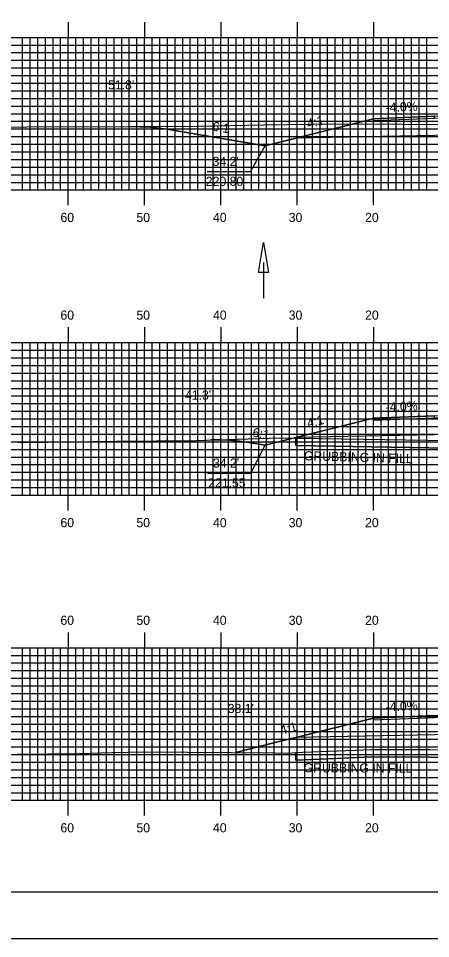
# Model space of a CAD drawing. Extents: x 1804684 to 1805027, y 442591 to 442811.
# Drawn here: x 1804783.1 to 1804837.2, y 442590.5 to 442711.2 of the extents above; entities that cross this region are included whole.
import ezdxf

# ---------------------------------------------------------------- set-up
doc = ezdxf.new("R2010")
doc.units = 0
for name, color, linetype in [('ANNOTATION', 7, 'Continuous'), ('BORDER', 7, 'Continuous'), ('D_Drainage_Ditch_Line', 7, 'Continuous'), ('D_Roadway_Centerline', 7, 'Continuous'), ('D_Roadway_Edge_Shoulder', 7, 'Continuous'), ('D_Roadway_SlopeLines', 7, 'Continuous'), ('D_Roadway_SubGrade', 7, 'Continuous'), ('D_Text_Standard', 7, 'Continuous'), ('GRUBBING IN FILL', 7, 'Continuous'), ('H_V ANNOTATION', 7, 'Continuous'), ('MAJOR', 7, 'Continuous'), ('MINOR', 7, 'Continuous'), ('PLOT BOUNDARY', 7, 'Continuous'), ('S_Roadway_Centerline', 7, 'Continuous')]:
    doc.layers.add(name, color=color, linetype=linetype)

msp = doc.modelspace()

# ---------------------------------------------------------------- linework, layer by layer
at = {"layer": 'ANNOTATION'}
for points in [[(1804807.87, 442691.09), (1804813.56, 442691.09), (1804815.51, 442694.47)], [(1804807.91, 442651.56), (1804813.61, 442651.56), (1804815.51, 442655.21)]]:
    msp.add_lwpolyline(points, dxfattribs=at)
at = {"layer": 'BORDER'}
msp.add_lwpolyline([(1804700.08, 442596.67), (1805020.08, 442596.67), (1805020.08, 442806.67), (1804700.08, 442806.67)], close=True, dxfattribs=at)
at = {"layer": 'D_Drainage_Ditch_Line'}
msp.add_line((1804815.28, 442679.18), (1804815.28, 442674.48), dxfattribs=at)
msp.add_lwpolyline([(1804815.94, 442677.86), (1804814.63, 442677.86), (1804815.28, 442681.8)], close=True, dxfattribs=at)
at = {"layer": 'D_Roadway_Centerline'}
for points in [[(1804797.85, 442696.98), (1804799.1, 442696.96), (1804800.35, 442696.89), (1804801.6, 442696.76), (1804802.85, 442696.58), (1804815.51, 442694.47), (1804819.51, 442695.47), (1804829.68, 442698.01), (1804837.68, 442698.33), (1804849.68, 442698.62), (1804861.68, 442698.91), (1804869.68, 442698.59), (1804879.85, 442696.04), (1804883.85, 442695.04), (1804901.29, 442697.95), (1804902.54, 442698.13), (1804903.79, 442698.25), (1804905.04, 442698.31), (1804906.29, 442698.31)], [(1804808.37, 442655.9), (1804809.62, 442655.91), (1804810.87, 442655.86), (1804812.12, 442655.74), (1804813.37, 442655.57), (1804815.51, 442655.21), (1804819.51, 442656.21), (1804829.68, 442658.75), (1804837.68, 442659.07), (1804849.68, 442659.36), (1804861.68, 442659.65), (1804869.68, 442659.33), (1804879.85, 442656.79), (1804883.85, 442655.79), (1804888.24, 442656.52), (1804889.49, 442656.7), (1804890.74, 442656.83), (1804891.99, 442656.91), (1804893.24, 442656.94)], [(1804811.62, 442614.93), (1804817.68, 442616.45), (1804819.51, 442616.91), (1804829.68, 442619.45), (1804837.68, 442619.77), (1804849.68, 442620.06), (1804861.68, 442620.35), (1804869.68, 442620.03), (1804879.85, 442617.48), (1804887.96, 442615.46)]]:
    msp.add_lwpolyline(points, dxfattribs=at)
at = {"layer": 'D_Roadway_Edge_Shoulder'}
for points in [[(1804837.68, 442698.33), (1804829.68, 442698.01), (1804829.68, 442697.76), (1804837.68, 442698.08)], [(1804837.68, 442659.07), (1804829.68, 442658.75), (1804829.68, 442658.5), (1804837.68, 442658.82)], [(1804837.68, 442619.77), (1804829.68, 442619.45), (1804829.68, 442619.2), (1804837.68, 442619.52)]]:
    msp.add_lwpolyline(points, close=True, dxfattribs=at)
at = {"layer": 'D_Roadway_SlopeLines'}
for points in [[(1804829.68, 442698.01), (1804815.51, 442694.47)], [(1804815.51, 442694.47), (1804802.85, 442696.58), (1804801.6, 442696.76), (1804800.35, 442696.89), (1804799.1, 442696.96), (1804797.85, 442696.98)], [(1804829.68, 442658.75), (1804815.51, 442655.21)], [(1804815.51, 442655.21), (1804813.37, 442655.57), (1804812.12, 442655.74), (1804810.87, 442655.86), (1804809.62, 442655.91), (1804808.37, 442655.9)], [(1804815.51, 442655.21), (1804812.12, 442655.74), (1804810.87, 442655.86), (1804809.62, 442655.91), (1804808.37, 442655.9)], [(1804829.68, 442619.45), (1804819.51, 442616.91), (1804817.68, 442616.45), (1804811.62, 442614.93)]]:
    msp.add_lwpolyline(points, dxfattribs=at)
at = {"layer": 'D_Roadway_SubGrade'}
for points in [[(1804837.68, 442695.83), (1804819.51, 442695.47), (1804829.68, 442698.01), (1804829.68, 442697.76), (1804837.68, 442698.08), (1804849.68, 442698.37), (1804861.68, 442698.66), (1804869.68, 442698.34), (1804869.68, 442698.59), (1804879.85, 442696.04), (1804861.68, 442696.41), (1804849.68, 442696.12)], [(1804837.68, 442656.57), (1804819.51, 442656.21), (1804829.68, 442658.75), (1804829.68, 442658.5), (1804837.68, 442658.82), (1804849.68, 442659.11), (1804861.68, 442659.4), (1804869.68, 442659.08), (1804869.68, 442659.33), (1804879.85, 442656.79), (1804861.68, 442657.15), (1804849.68, 442656.86)], [(1804837.68, 442617.27), (1804819.51, 442616.91), (1804829.68, 442619.45), (1804829.68, 442619.2), (1804837.68, 442619.52), (1804849.68, 442619.81), (1804861.68, 442620.1), (1804869.68, 442619.78), (1804869.68, 442620.03), (1804879.85, 442617.48), (1804861.68, 442617.85), (1804849.68, 442617.56)]]:
    msp.add_lwpolyline(points, close=True, dxfattribs=at)
at = {"layer": 'GRUBBING IN FILL'}
for p, q in [((1804819.51, 442656.16), (1804819.51, 442655.16)), ((1804819.51, 442656.16), (1804819.51, 442655.16)), ((1804819.51, 442614.93), (1804819.51, 442613.93)), ((1804819.51, 442614.93), (1804819.51, 442613.93))]:
    msp.add_line(p, q, dxfattribs=at)
for points in [[(1804819.51, 442656.16), (1804828.42, 442656.02), (1804839.46, 442655.84), (1804841.42, 442655.85), (1804849.68, 442656), (1804849.68, 442654.99), (1804841.43, 442654.85), (1804839.45, 442654.84), (1804829.48, 442655), (1804819.51, 442655.16)], [(1804819.51, 442656.16), (1804828.42, 442656.02), (1804839.46, 442655.84), (1804841.42, 442655.85), (1804849.68, 442656), (1804849.68, 442654.99), (1804841.43, 442654.85), (1804839.45, 442654.84), (1804829.48, 442655), (1804819.51, 442655.16)], [(1804819.51, 442614.93), (1804820.41, 442614.99), (1804824.93, 442615.17), (1804829.44, 442615.35), (1804833.26, 442615.34), (1804837.08, 442615.32), (1804840.97, 442615.2), (1804844.86, 442615.08), (1804849.68, 442615.12), (1804849.68, 442614.12), (1804844.85, 442614.08), (1804840.96, 442614.2), (1804837.06, 442614.32), (1804833.26, 442614.34), (1804829.46, 442614.35), (1804824.96, 442614.17), (1804819.51, 442613.93)], [(1804819.51, 442614.93), (1804820.41, 442614.99), (1804824.93, 442615.17), (1804829.44, 442615.35), (1804833.26, 442615.34), (1804837.08, 442615.32), (1804840.97, 442615.2), (1804844.86, 442615.08), (1804849.68, 442615.12), (1804849.68, 442614.12), (1804844.85, 442614.08), (1804840.96, 442614.2), (1804837.06, 442614.32), (1804833.26, 442614.34), (1804829.46, 442614.35), (1804824.96, 442614.17), (1804819.51, 442613.93)]]:
    msp.add_lwpolyline(points, close=True, dxfattribs=at)
for points in [[(1804819.51, 442655.16), (1804839.45, 442654.84), (1804840.48, 442654.85), (1804841.43, 442654.85), (1804858.38, 442655.14), (1804864.95, 442655.26), (1804865.14, 442655.25), (1804879.85, 442655.7)], [(1804819.51, 442655.16), (1804839.45, 442654.84), (1804840.48, 442654.85), (1804841.43, 442654.85), (1804858.38, 442655.14), (1804864.95, 442655.26), (1804865.14, 442655.25), (1804879.85, 442655.7)], [(1804819.51, 442613.93), (1804820.46, 442613.99), (1804829.46, 442614.35), (1804837.06, 442614.32), (1804844.85, 442614.08), (1804861.41, 442614.21), (1804867.45, 442614.4), (1804876.43, 442614.59), (1804879.85, 442614.57)], [(1804819.51, 442613.93), (1804820.46, 442613.99), (1804829.46, 442614.35), (1804837.06, 442614.32), (1804844.85, 442614.08), (1804861.41, 442614.21), (1804867.45, 442614.4), (1804876.43, 442614.59), (1804879.85, 442614.57)]]:
    msp.add_lwpolyline(points, dxfattribs=at)
at = {"layer": 'MAJOR'}
for p, q in [((1804789.68, 442710.67), (1804789.68, 442708.67)), ((1804799.68, 442710.67), (1804799.68, 442708.67)), ((1804809.68, 442710.67), (1804809.68, 442708.67)), ((1804819.68, 442710.67), (1804819.68, 442708.67)), ((1804829.68, 442710.67), (1804829.68, 442708.67)), ((1804709.68, 442708.67), (1804989.68, 442708.67)), ((1804709.68, 442708.67), (1804989.68, 442708.67)), ((1804789.68, 442688.67), (1804789.68, 442708.67)), ((1804799.68, 442688.67), (1804799.68, 442708.67)), ((1804809.68, 442688.67), (1804809.68, 442708.67)), ((1804819.68, 442688.67), (1804819.68, 442708.67)), ((1804829.68, 442688.67), (1804829.68, 442708.67)), ((1804709.68, 442703.67), (1804989.68, 442703.67)), ((1804709.68, 442698.67), (1804989.68, 442698.67)), ((1804709.68, 442693.67), (1804989.68, 442693.67)), ((1804709.68, 442688.67), (1804989.68, 442688.67)), ((1804709.68, 442688.67), (1804989.68, 442688.67)), ((1804789.68, 442686.66), (1804789.68, 442688.67)), ((1804799.68, 442686.66), (1804799.68, 442688.67)), ((1804809.68, 442686.66), (1804809.68, 442688.67)), ((1804819.68, 442686.66), (1804819.68, 442688.67)), ((1804829.68, 442686.66), (1804829.68, 442688.67)), ((1804789.68, 442670.67), (1804789.68, 442668.67)), ((1804799.68, 442670.67), (1804799.68, 442668.67)), ((1804809.68, 442670.67), (1804809.68, 442668.67)), ((1804819.68, 442670.67), (1804819.68, 442668.67)), ((1804829.68, 442670.67), (1804829.68, 442668.67)), ((1804709.68, 442668.67), (1804989.68, 442668.67)), ((1804709.68, 442668.67), (1804989.68, 442668.67)), ((1804789.68, 442648.67), (1804789.68, 442668.67)), ((1804799.68, 442648.67), (1804799.68, 442668.67)), ((1804809.68, 442648.67), (1804809.68, 442668.67)), ((1804819.68, 442648.67), (1804819.68, 442668.67)), ((1804829.68, 442648.67), (1804829.68, 442668.67)), ((1804709.68, 442663.67), (1804989.68, 442663.67)), ((1804709.68, 442658.67), (1804989.68, 442658.67)), ((1804709.68, 442653.67), (1804989.68, 442653.67)), ((1804709.68, 442648.67), (1804989.68, 442648.67)), ((1804709.68, 442648.67), (1804989.68, 442648.67)), ((1804789.68, 442646.66), (1804789.68, 442648.67)), ((1804799.68, 442646.66), (1804799.68, 442648.67)), ((1804809.68, 442646.66), (1804809.68, 442648.67)), ((1804819.68, 442646.66), (1804819.68, 442648.67)), ((1804829.68, 442646.66), (1804829.68, 442648.67)), ((1804789.68, 442630.67), (1804789.68, 442628.67)), ((1804799.68, 442630.67), (1804799.68, 442628.67)), ((1804809.68, 442630.67), (1804809.68, 442628.67)), ((1804819.68, 442630.67), (1804819.68, 442628.67)), ((1804829.68, 442630.67), (1804829.68, 442628.67)), ((1804709.68, 442628.67), (1804989.68, 442628.67)), ((1804709.68, 442628.67), (1804989.68, 442628.67)), ((1804789.68, 442608.67), (1804789.68, 442628.67)), ((1804799.68, 442608.67), (1804799.68, 442628.67)), ((1804809.68, 442608.67), (1804809.68, 442628.67)), ((1804819.68, 442608.67), (1804819.68, 442628.67)), ((1804829.68, 442608.67), (1804829.68, 442628.67)), ((1804709.68, 442623.67), (1804989.68, 442623.67)), ((1804709.68, 442618.67), (1804989.68, 442618.67)), ((1804709.68, 442613.67), (1804989.68, 442613.67)), ((1804709.68, 442608.67), (1804989.68, 442608.67)), ((1804709.68, 442608.67), (1804989.68, 442608.67)), ((1804789.68, 442606.66), (1804789.68, 442608.67)), ((1804799.68, 442606.66), (1804799.68, 442608.67)), ((1804809.68, 442606.66), (1804809.68, 442608.67)), ((1804819.68, 442606.66), (1804819.68, 442608.67)), ((1804829.68, 442606.66), (1804829.68, 442608.67))]:
    msp.add_line(p, q, dxfattribs=at)
at = {"layer": 'MINOR'}
for p, q in [((1804783.68, 442688.67), (1804783.68, 442708.67)), ((1804784.68, 442688.67), (1804784.68, 442708.67)), ((1804785.68, 442688.67), (1804785.68, 442708.67)), ((1804786.68, 442688.67), (1804786.68, 442708.67)), ((1804787.68, 442688.67), (1804787.68, 442708.67)), ((1804788.68, 442688.67), (1804788.68, 442708.67)), ((1804790.68, 442688.67), (1804790.68, 442708.67)), ((1804791.68, 442688.67), (1804791.68, 442708.67)), ((1804792.68, 442688.67), (1804792.68, 442708.67)), ((1804793.68, 442688.67), (1804793.68, 442708.67)), ((1804794.68, 442688.67), (1804794.68, 442708.67)), ((1804795.68, 442688.67), (1804795.68, 442708.67)), ((1804796.68, 442688.67), (1804796.68, 442708.67)), ((1804797.68, 442688.67), (1804797.68, 442708.67)), ((1804798.68, 442688.67), (1804798.68, 442708.67)), ((1804800.68, 442688.67), (1804800.68, 442708.67)), ((1804801.68, 442688.67), (1804801.68, 442708.67)), ((1804802.68, 442688.67), (1804802.68, 442708.67)), ((1804803.68, 442688.67), (1804803.68, 442708.67)), ((1804804.68, 442688.67), (1804804.68, 442708.67)), ((1804805.68, 442688.67), (1804805.68, 442708.67)), ((1804806.68, 442688.67), (1804806.68, 442708.67)), ((1804807.68, 442688.67), (1804807.68, 442708.67)), ((1804808.68, 442688.67), (1804808.68, 442708.67)), ((1804810.68, 442688.67), (1804810.68, 442708.67)), ((1804811.68, 442688.67), (1804811.68, 442708.67)), ((1804812.68, 442688.67), (1804812.68, 442708.67)), ((1804813.68, 442688.67), (1804813.68, 442708.67)), ((1804814.68, 442688.67), (1804814.68, 442708.67)), ((1804815.68, 442688.67), (1804815.68, 442708.67)), ((1804816.68, 442688.67), (1804816.68, 442708.67)), ((1804817.68, 442688.67), (1804817.68, 442708.67)), ((1804818.68, 442688.67), (1804818.68, 442708.67)), ((1804820.68, 442688.67), (1804820.68, 442708.67)), ((1804821.68, 442688.67), (1804821.68, 442708.67)), ((1804822.68, 442688.67), (1804822.68, 442708.67)), ((1804823.68, 442688.67), (1804823.68, 442708.67)), ((1804824.68, 442688.67), (1804824.68, 442708.67)), ((1804825.68, 442688.67), (1804825.68, 442708.67)), ((1804826.68, 442688.67), (1804826.68, 442708.67)), ((1804827.68, 442688.67), (1804827.68, 442708.67)), ((1804828.68, 442688.67), (1804828.68, 442708.67)), ((1804830.68, 442688.67), (1804830.68, 442708.67)), ((1804831.68, 442688.67), (1804831.68, 442708.67)), ((1804832.68, 442688.67), (1804832.68, 442708.67)), ((1804833.68, 442688.67), (1804833.68, 442708.67)), ((1804834.68, 442688.67), (1804834.68, 442708.67)), ((1804835.68, 442688.67), (1804835.68, 442708.67)), ((1804836.68, 442688.67), (1804836.68, 442708.67)), ((1804709.68, 442707.67), (1804989.68, 442707.67)), ((1804709.68, 442706.67), (1804989.68, 442706.67)), ((1804709.68, 442705.67), (1804989.68, 442705.67)), ((1804709.68, 442704.67), (1804989.68, 442704.67)), ((1804709.68, 442702.67), (1804989.68, 442702.67)), ((1804709.68, 442701.67), (1804989.68, 442701.67)), ((1804709.68, 442700.67), (1804989.68, 442700.67)), ((1804709.68, 442699.67), (1804989.68, 442699.67)), ((1804709.68, 442697.67), (1804989.68, 442697.67)), ((1804709.68, 442696.67), (1804989.68, 442696.67)), ((1804709.68, 442695.67), (1804989.68, 442695.67)), ((1804709.68, 442694.67), (1804989.68, 442694.67)), ((1804709.68, 442692.67), (1804989.68, 442692.67)), ((1804709.68, 442691.67), (1804989.68, 442691.67)), ((1804709.68, 442690.67), (1804989.68, 442690.67)), ((1804709.68, 442689.67), (1804989.68, 442689.67)), ((1804783.68, 442648.67), (1804783.68, 442668.67)), ((1804784.68, 442648.67), (1804784.68, 442668.67)), ((1804785.68, 442648.67), (1804785.68, 442668.67)), ((1804786.68, 442648.67), (1804786.68, 442668.67)), ((1804787.68, 442648.67), (1804787.68, 442668.67)), ((1804788.68, 442648.67), (1804788.68, 442668.67)), ((1804790.68, 442648.67), (1804790.68, 442668.67)), ((1804791.68, 442648.67), (1804791.68, 442668.67)), ((1804792.68, 442648.67), (1804792.68, 442668.67)), ((1804793.68, 442648.67), (1804793.68, 442668.67)), ((1804794.68, 442648.67), (1804794.68, 442668.67)), ((1804795.68, 442648.67), (1804795.68, 442668.67)), ((1804796.68, 442648.67), (1804796.68, 442668.67)), ((1804797.68, 442648.67), (1804797.68, 442668.67)), ((1804798.68, 442648.67), (1804798.68, 442668.67)), ((1804800.68, 442648.67), (1804800.68, 442668.67)), ((1804801.68, 442648.67), (1804801.68, 442668.67)), ((1804802.68, 442648.67), (1804802.68, 442668.67)), ((1804803.68, 442648.67), (1804803.68, 442668.67)), ((1804804.68, 442648.67), (1804804.68, 442668.67)), ((1804805.68, 442648.67), (1804805.68, 442668.67)), ((1804806.68, 442648.67), (1804806.68, 442668.67)), ((1804807.68, 442648.67), (1804807.68, 442668.67)), ((1804808.68, 442648.67), (1804808.68, 442668.67)), ((1804810.68, 442648.67), (1804810.68, 442668.67)), ((1804811.68, 442648.67), (1804811.68, 442668.67)), ((1804812.68, 442648.67), (1804812.68, 442668.67)), ((1804813.68, 442648.67), (1804813.68, 442668.67)), ((1804814.68, 442648.67), (1804814.68, 442668.67)), ((1804815.68, 442648.67), (1804815.68, 442668.67)), ((1804816.68, 442648.67), (1804816.68, 442668.67)), ((1804817.68, 442648.67), (1804817.68, 442668.67)), ((1804818.68, 442648.67), (1804818.68, 442668.67)), ((1804820.68, 442648.67), (1804820.68, 442668.67)), ((1804821.68, 442648.67), (1804821.68, 442668.67)), ((1804822.68, 442648.67), (1804822.68, 442668.67)), ((1804823.68, 442648.67), (1804823.68, 442668.67)), ((1804824.68, 442648.67), (1804824.68, 442668.67)), ((1804825.68, 442648.67), (1804825.68, 442668.67)), ((1804826.68, 442648.67), (1804826.68, 442668.67)), ((1804827.68, 442648.67), (1804827.68, 442668.67)), ((1804828.68, 442648.67), (1804828.68, 442668.67)), ((1804830.68, 442648.67), (1804830.68, 442668.67)), ((1804831.68, 442648.67), (1804831.68, 442668.67)), ((1804832.68, 442648.67), (1804832.68, 442668.67)), ((1804833.68, 442648.67), (1804833.68, 442668.67)), ((1804834.68, 442648.67), (1804834.68, 442668.67)), ((1804835.68, 442648.67), (1804835.68, 442668.67)), ((1804836.68, 442648.67), (1804836.68, 442668.67)), ((1804709.68, 442667.67), (1804989.68, 442667.67)), ((1804709.68, 442666.67), (1804989.68, 442666.67)), ((1804709.68, 442665.67), (1804989.68, 442665.67)), ((1804709.68, 442664.67), (1804989.68, 442664.67)), ((1804709.68, 442662.67), (1804989.68, 442662.67)), ((1804709.68, 442661.67), (1804989.68, 442661.67)), ((1804709.68, 442660.67), (1804989.68, 442660.67)), ((1804709.68, 442659.67), (1804989.68, 442659.67)), ((1804709.68, 442657.67), (1804989.68, 442657.67)), ((1804709.68, 442656.67), (1804989.68, 442656.67)), ((1804709.68, 442655.67), (1804989.68, 442655.67)), ((1804709.68, 442654.67), (1804989.68, 442654.67)), ((1804709.68, 442652.67), (1804989.68, 442652.67)), ((1804709.68, 442651.67), (1804989.68, 442651.67)), ((1804709.68, 442650.67), (1804989.68, 442650.67)), ((1804709.68, 442649.67), (1804989.68, 442649.67)), ((1804783.68, 442608.67), (1804783.68, 442628.67)), ((1804784.68, 442608.67), (1804784.68, 442628.67)), ((1804785.68, 442608.67), (1804785.68, 442628.67)), ((1804786.68, 442608.67), (1804786.68, 442628.67)), ((1804787.68, 442608.67), (1804787.68, 442628.67)), ((1804788.68, 442608.67), (1804788.68, 442628.67)), ((1804790.68, 442608.67), (1804790.68, 442628.67)), ((1804791.68, 442608.67), (1804791.68, 442628.67)), ((1804792.68, 442608.67), (1804792.68, 442628.67)), ((1804793.68, 442608.67), (1804793.68, 442628.67)), ((1804794.68, 442608.67), (1804794.68, 442628.67)), ((1804795.68, 442608.67), (1804795.68, 442628.67)), ((1804796.68, 442608.67), (1804796.68, 442628.67)), ((1804797.68, 442608.67), (1804797.68, 442628.67)), ((1804798.68, 442608.67), (1804798.68, 442628.67)), ((1804800.68, 442608.67), (1804800.68, 442628.67)), ((1804801.68, 442608.67), (1804801.68, 442628.67)), ((1804802.68, 442608.67), (1804802.68, 442628.67)), ((1804803.68, 442608.67), (1804803.68, 442628.67)), ((1804804.68, 442608.67), (1804804.68, 442628.67)), ((1804805.68, 442608.67), (1804805.68, 442628.67)), ((1804806.68, 442608.67), (1804806.68, 442628.67)), ((1804807.68, 442608.67), (1804807.68, 442628.67)), ((1804808.68, 442608.67), (1804808.68, 442628.67)), ((1804810.68, 442608.67), (1804810.68, 442628.67)), ((1804811.68, 442608.67), (1804811.68, 442628.67)), ((1804812.68, 442608.67), (1804812.68, 442628.67)), ((1804813.68, 442608.67), (1804813.68, 442628.67)), ((1804814.68, 442608.67), (1804814.68, 442628.67)), ((1804815.68, 442608.67), (1804815.68, 442628.67)), ((1804816.68, 442608.67), (1804816.68, 442628.67)), ((1804817.68, 442608.67), (1804817.68, 442628.67)), ((1804818.68, 442608.67), (1804818.68, 442628.67)), ((1804820.68, 442608.67), (1804820.68, 442628.67)), ((1804821.68, 442608.67), (1804821.68, 442628.67)), ((1804822.68, 442608.67), (1804822.68, 442628.67)), ((1804823.68, 442608.67), (1804823.68, 442628.67)), ((1804824.68, 442608.67), (1804824.68, 442628.67)), ((1804825.68, 442608.67), (1804825.68, 442628.67)), ((1804826.68, 442608.67), (1804826.68, 442628.67)), ((1804827.68, 442608.67), (1804827.68, 442628.67)), ((1804828.68, 442608.67), (1804828.68, 442628.67)), ((1804830.68, 442608.67), (1804830.68, 442628.67)), ((1804831.68, 442608.67), (1804831.68, 442628.67)), ((1804832.68, 442608.67), (1804832.68, 442628.67)), ((1804833.68, 442608.67), (1804833.68, 442628.67)), ((1804834.68, 442608.67), (1804834.68, 442628.67)), ((1804835.68, 442608.67), (1804835.68, 442628.67)), ((1804836.68, 442608.67), (1804836.68, 442628.67)), ((1804709.68, 442627.67), (1804989.68, 442627.67)), ((1804709.68, 442626.67), (1804989.68, 442626.67)), ((1804709.68, 442625.67), (1804989.68, 442625.67)), ((1804709.68, 442624.67), (1804989.68, 442624.67)), ((1804709.68, 442622.67), (1804989.68, 442622.67)), ((1804709.68, 442621.67), (1804989.68, 442621.67)), ((1804709.68, 442620.67), (1804989.68, 442620.67)), ((1804709.68, 442619.67), (1804989.68, 442619.67)), ((1804709.68, 442617.67), (1804989.68, 442617.67)), ((1804709.68, 442616.67), (1804989.68, 442616.67)), ((1804709.68, 442615.67), (1804989.68, 442615.67)), ((1804709.68, 442614.67), (1804989.68, 442614.67)), ((1804709.68, 442612.67), (1804989.68, 442612.67)), ((1804709.68, 442611.67), (1804989.68, 442611.67)), ((1804709.68, 442610.67), (1804989.68, 442610.67)), ((1804709.68, 442609.67), (1804989.68, 442609.67))]:
    msp.add_line(p, q, dxfattribs=at)
at = {"layer": 'PLOT BOUNDARY'}
msp.add_lwpolyline([(1804683.89, 442590.55), (1805023.89, 442590.55), (1805023.89, 442810.55), (1804683.89, 442810.55)], close=True, dxfattribs=at)
at = {"layer": 'S_Roadway_Centerline'}
for points in [[(1804774.87, 442696.86), (1804784.25, 442696.94), (1804798.89, 442696.98), (1804806.64, 442697.05), (1804815.33, 442697.21), (1804821.41, 442697.28), (1804829.59, 442697.33), (1804837.34, 442697.27), (1804853.74, 442697.41), (1804861.11, 442698.35), (1804868.67, 442698.5), (1804876.82, 442697.88), (1804884.86, 442698.44), (1804889.08, 442698.45), (1804893.32, 442698.59), (1804906.83, 442698.3), (1804911.96, 442698.24)], [(1804772.62, 442656.11), (1804784.02, 442655.57), (1804795.94, 442655.76), (1804806.45, 442655.84), (1804817.38, 442656.2), (1804839.46, 442655.84), (1804840.47, 442655.85), (1804841.42, 442655.85), (1804858.36, 442656.14), (1804864.97, 442656.26), (1804865.15, 442656.25), (1804883.79, 442656.82), (1804887.57, 442656.93), (1804887.62, 442656.93), (1804887.64, 442656.93), (1804895.71, 442656.94), (1804911.53, 442656.95)], [(1804783.04, 442614.74), (1804791.17, 442614.81), (1804795.42, 442614.92), (1804799.52, 442615.02), (1804816.79, 442614.9), (1804818.39, 442614.86), (1804820.41, 442614.99), (1804829.44, 442615.35), (1804837.08, 442615.32), (1804844.86, 442615.08), (1804861.39, 442615.21), (1804867.42, 442615.4), (1804876.42, 442615.6), (1804884.65, 442615.53), (1804888.3, 442615.45), (1804892.04, 442615.5), (1804899.88, 442615.45), (1804908.7, 442615.36), (1804914.14, 442615.38)]]:
    msp.add_lwpolyline(points, dxfattribs=at)

# ---------------------------------------------------------------- texts
at = {"layer": 'ANNOTATION'}
for s, rotation, p in [('-4.0%', 2.2906, (1804831.31, 442698.88)), ('4:1', 14.0362, (1804821.13, 442696.74)), ('6:1', 350.5376, (1804808.51, 442696.46)), ('-4.0%', 2.2906, (1804831.31, 442659.62)), ('4:1', 14.0362, (1804821.13, 442657.48)), ('6:1', 350.5377, (1804813.77, 442656.33)), ('-4.0%', 2.2906, (1804831.31, 442620.32)), ('4:1', 14.0362, (1804817.6, 442617.26))]:
    msp.add_text(s, height=1.2, rotation=rotation, dxfattribs=at).set_placement(p)
for s, p in [("34.2'", (1804808.6, 442691.81)), ('220.80', (1804807.71, 442689.21)), ("34.2'", (1804808.65, 442652.28)), ('221.55', (1804808.02, 442649.68))]:
    msp.add_text(s, height=1.2, dxfattribs=at).set_placement(p)
at = {"layer": 'D_Text_Standard'}
for s, p in [("51.8'", (1804794.89, 442701.86)), ("41.3'", (1804804.98, 442661.19)), ("38.1'", (1804810.58, 442620.11))]:
    msp.add_text(s, height=1.2, dxfattribs=at).set_placement(p)
at = {"layer": 'GRUBBING IN FILL'}
for rotation, p in [(358.4339, (1804820.56, 442653.24)), (359.8053, (1804820.53, 442612.34))]:
    msp.add_text('GRUBBING IN FILL', height=1.2, rotation=rotation, dxfattribs=at).set_placement(p)
at = {"layer": 'H_V ANNOTATION'}
for s, p in [('60', (1804788.65, 442684.47)), ('50', (1804798.61, 442684.47)), ('40', (1804808.65, 442684.47)), ('30', (1804818.58, 442684.47)), ('20', (1804828.59, 442684.47)), ('60', (1804788.65, 442671.67)), ('50', (1804798.61, 442671.67)), ('40', (1804808.65, 442671.67)), ('30', (1804818.58, 442671.67)), ('20', (1804828.59, 442671.67)), ('60', (1804788.65, 442644.47)), ('50', (1804798.61, 442644.47)), ('40', (1804808.65, 442644.47)), ('30', (1804818.58, 442644.47)), ('20', (1804828.59, 442644.47)), ('60', (1804788.65, 442631.67)), ('50', (1804798.61, 442631.67)), ('40', (1804808.65, 442631.67)), ('30', (1804818.58, 442631.67)), ('20', (1804828.59, 442631.67)), ('60', (1804788.65, 442604.47)), ('50', (1804798.61, 442604.47)), ('40', (1804808.65, 442604.47)), ('30', (1804818.58, 442604.47)), ('20', (1804828.59, 442604.47))]:
    msp.add_text(s, height=1.2, dxfattribs=at).set_placement(p)

doc.saveas('drawing.dxf')
